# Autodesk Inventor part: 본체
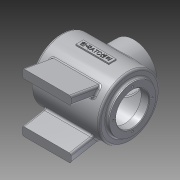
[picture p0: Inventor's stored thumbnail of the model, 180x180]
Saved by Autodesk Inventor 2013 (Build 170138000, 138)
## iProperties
Created: 2015-01
Part Number: 본체
Material: 알루미늄 6061
Document SubType Name: Modeling
Designer: Administrator
Density: 2.71 g/cm^3
Mass: 1021.43 g
Surface Area: 1058.43 cm^2
Volume: 376.91 cm^3
Author: Administrator
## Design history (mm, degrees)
sketch "스케치4"
  geometry: L1 (-62, -38)-(60, -38); L2 (60, -38)-(60, 38); L3 (60, 38)-(-62, 38); L4 (-62, 38)-(-62, -38); 2 further points
  constraints: 8 end point, 2 parallel, 1 horizontal, 1 horizontal alignment, 1 midpoint, 1 perpendicular
  dimensions: "d4" = 60 distance from line of L2 point (0, 0); "d5" = 122 distance of L1.start L1.end; "d6" = 76 distance of L3.end L1.start
extrude "돌출1" new body sketch "스케치4" stored distance "d7" = 76; taper "d8" = 0 deg
fillet "모깎기1" dims "d9" = 38
sketch "스케치5"
  geometry: L1 (-57, -50)-(55, -50); L2 (55, -50)-(55, 50); L3 (55, 50)-(-57, 50); L4 (-57, 50)-(-57, -50); L5 (-62, -38)-(-62, 38) reference; L6 (-62, 38)-(60, 38) reference; L7 (60, 38)-(60, -38) reference; L8 (60, -38)-(-62, -38) reference; 2 further points
  constraints: 8 end point, 2 parallel, 1 horizontal, 1 horizontal alignment, 1 midpoint, 1 perpendicular
  dimensions: "d10" = 112 distance of L1.start L1.end; "d12" = 100 distance of L1.end L2.end; "d13" = 5 distance between parallel lines of L5 L4
extrude "돌출2" join sketch "스케치5" stored distance "d14" = 100; taper "d15" = 0 deg
fillet "모깎기2" dims "d16" = 50
node "작업 평면1"
sketch "스케치7"
  geometry: C1 r 45 at (0, 0); 1 further point
  constraints: 1 centre point, 1 coincident
  dimensions: "d22" = 90 diameter of C1
extrude "돌출3" cut sketch "스케치7" distance "d23" = 97; taper "d24" = 0 deg
node "작업 평면2"
sketch "스케치8"
  geometry: L1 (-60, -38)-(-60, 38) reference; C1 r 38 at (0, 0); 1 further point
  constraints: 1 centre point, 1 coincident
  dimensions: "d26" = 76 diameter of C1
extrude "돌출4" join sketch "스케치8" stored distance "d27" = 97; taper "d28" = 0 deg
fillet "모깎기3" dims "d29" = 3
sketch "스케치9"
  geometry: C1 r 27 at (0, 0); 1 further point
  constraints: 1 centre point, 1 coincident
  dimensions: "d30" = 54 diameter of C1
extrude "돌출5" cut sketch "스케치9" stored distance "d31" = 97; taper "d32" = 0 deg
sketch "스케치10"
  geometry: C1 r 27 at (0, 0); 1 further point
  constraints: 1 centre point, 1 coincident
  dimensions: "d33" = 54 diameter of C1
extrude "돌출6" cut sketch "스케치10" stored distance "d34" = 97; taper "d35" = 0 deg
sketch "스케치11"
  geometry: 2 further points
  constraints: 1 vertical alignment
  dimensions: "d36" = 32 distance of point (0, 0) point (0, 32)
hole "구멍1" sketch "스케치11" at (0, 32) diameter "d37" = 3.242; stored, may be unused: countersink angle "d41" = 90 deg, drill point angle "d43" = 118 deg; dims "d38" = 8, "d39" = 4, "d40" = 2, "d42" = 10
node "작업 평면3"
sketch "스케치12"
  geometry: 2 further points
  constraints: 1 vertical alignment
  dimensions: "d47" = 32 distance of point (0, 0) point (0, 32)
hole "구멍2" sketch "스케치12" at (0, 32) diameter "d48" = 3.242; stored, may be unused: countersink angle "d52" = 90 deg, drill point angle "d54" = 118 deg; dims "d49" = 8, "d50" = 4, "d51" = 2, "d53" = 10
sketch "스케치13"
  geometry: L1 (27.282, -41.901)-(34, -80); L2 (34, -80)-(48, -80); L3 (48, -80)-(39.336, -30.865); A1 r 50 centre (0, 0) between (39.336, -30.865) and (27.282, -41.901) reference; 1 further point
  constraints: 6 end point, 2 point on circle, 1 horizontal, 1 parallel
  dimensions: "d58" = 80 distance from line of L2 point (0, 0); "d59" = 100 deg angle of L2 L3; "d60" = 14 distance of L1.end L2.end; "d61" = 48 horizontal distance of point (0, 0) L2.end
extrude "돌출7" join sketch "스케치13" stored distance "d62" = 80; taper "d63" = 0 deg
fillet "모깎기4" dims "d64" = 3
fillet "모깎기5" dims "d65" = 3
chamfer "모따기1" distance "d66" = 1; stored, may be unused: second distance "d67" = 2, angle "d68" = 45 deg
node "작업 평면4"
sketch "스케치14"
  geometry: L1 (-27, -6)-(27, -6); L2 (27, -6)-(27, 6); L3 (27, 6)-(-27, 6); L4 (-27, 6)-(-27, -6); 3 further points
  constraints: 8 end point, 2 midpoint, 2 parallel, 1 horizontal, 1 horizontal alignment, 1 perpendicular, 1 vertical alignment
  dimensions: "d70" = 54 distance of L3.end L2.end; "d71" = 12 distance of L2.end L1.end
extrude "돌출8" join sketch "스케치14" stored distance "d72" = 80; taper "d73" = 0 deg
sketch "스케치15"
  geometry: 2 further points
  constraints: 1 coincident, 1 other
feature "엠보싱1" sketch "스케치15" dims "d4" = 60, "d5" = 122, "d6" = 76, "d74" = 0.5, "d75" = 0
node "솔리드1"
pattern_circular "원형 패턴1" dims angle "d45" = 360 deg
mirror "대칭1"
pattern_circular "원형 패턴2" dims angle "d56" = 360 deg
mirror "대칭2"
node "절단 모서리 투영1"
other parameters: "d21" = -12, "d25" = 62, "d69" = 52
